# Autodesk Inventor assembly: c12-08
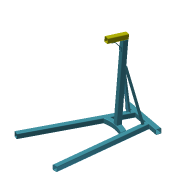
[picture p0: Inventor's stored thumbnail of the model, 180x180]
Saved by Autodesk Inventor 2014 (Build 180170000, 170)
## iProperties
Created: 2011-01
Part Number: c12-08
Document SubType Name: Assembly
Designer: Thom Tremblay
_SolveAssemblyDoc: Frame Generator Solve Assembly
_Version: 15.0.0
Author: Thom Tremblay
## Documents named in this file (3)
- C:\Inventor 2014 Essentials\Assemblies\Chapter 12\c12-08.iam
- C:\Inventor 2014 Essentials\Assemblies\Chapter 12\Frame\Frame c12-08.iam
- C:\Inventor 2014 Essentials\Parts\Chapter 12\c12-02.ipt
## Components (2 placed, 2 different names)
1. c12-02:1
2. Frame c12-08:1 [sub-assembly]
